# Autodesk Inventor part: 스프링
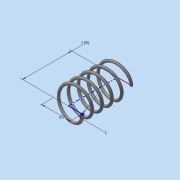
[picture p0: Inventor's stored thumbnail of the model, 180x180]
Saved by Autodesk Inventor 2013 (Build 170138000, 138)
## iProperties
Created: 2015-10
Part Number: 스프링
Material: 일반
Document SubType Name: Modeling
Designer: dgall
Density: 1 g/cm^3
Mass: 0.13407 g
Surface Area: 5.42648 cm^2
Volume: 0.13407 cm^3
Author: dgall
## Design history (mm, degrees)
sketch "스케치1"
  geometry: L1 (0, 0)-(0, 18.948); L2 (0, 18.948)-(5.5, 18.948); L3 (0, 0)-(5.5, 0); C1 r 0.5 at (5.5, 0)
  constraints: 6 end point, 1 centre point, 1 coincident, 1 parallel, 1 perpendicular, 1 vertical, 1 vertical alignment
  dimensions: "d0" = 1 diameter of C1; "d1" = 18.94782 distance of L1.start L1.end (derived); "d2" = 11 diameter of L3.end L1
feature "코일1" pitch "d3" = 10; turns "d5" = 5; dims "d4" = 18.94782 (= d1), "d6" = 0, angle "d7" = 90 deg, angle "d8" = 90 deg, "d9" = 0, "d10" = 0
feature "분할1"
node "작업 평면1"
feature "분할2"
node "솔리드1"
other parameters: "d11" = 19
